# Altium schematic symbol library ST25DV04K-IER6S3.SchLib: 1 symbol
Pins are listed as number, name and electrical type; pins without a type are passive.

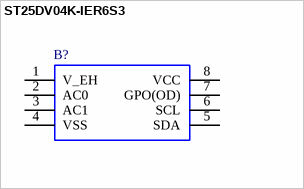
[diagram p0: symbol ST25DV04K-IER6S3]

## ST25DV04K-IER6S3
designator B?
STMICROELECTRONICS - ST25DV04K-IER6S3 - RFID/NFC IC, 13.553 MHz to 13.567 MHz, Read, Write, 4Kbit, I2C, 1.8 V to 5.5 V, SOIC-8; Geometry.Height: 1.75mm
footprint SOIC127P600X175-8N
pins: 1 V_EH, 2 AC0, 3 AC1, 4 VSS, 5 SDA, 6 SCL, 7 GPO(OD), 8 VCC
